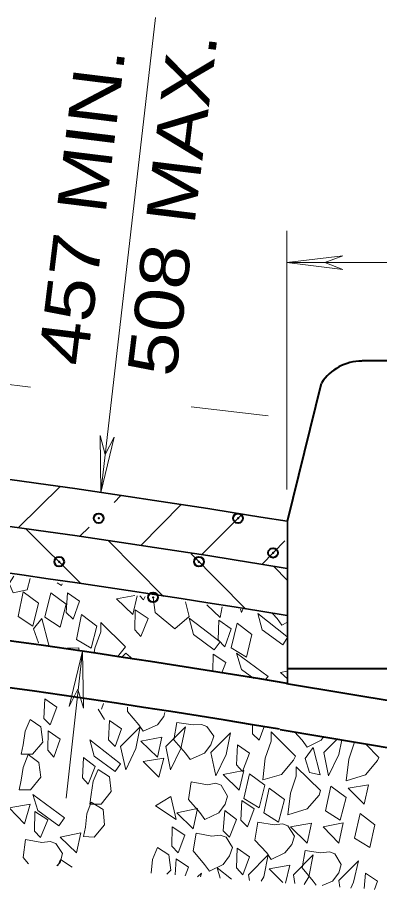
# Model space of a CAD drawing. Extents: x 312583 to 312854, y 144419 to 144597.
# Drawn here: x 312697.85 to 312703.46, y 144439.22 to 144452.74 of the extents above; entities that cross this region are included whole.
import ezdxf

# ---------------------------------------------------------------- set-up
doc = ezdxf.new("R2010")
doc.units = 0
doc.header["$LTSCALE"] = 0.3
doc.header["$PDMODE"] = 32
doc.header["$PDSIZE"] = 0.15
doc.layers.add('1', color=7, linetype='Continuous', lineweight=40)
doc.layers.add('2', color=7, linetype='Continuous', lineweight=13)

msp = doc.modelspace()

# ---------------------------------------------------------------- linework, layer by layer
at = {"layer": '1', "lineweight": 13}
for p, q in [((312697.8645, 144444.8297), (312698.5085, 144445.4661)), ((312699.3442, 144445.2207), (312699.4515, 144445.3281)), ((312699.7582, 144444.5537), (312700.3868, 144445.1901)), ((312700.7012, 144444.4081), (312701.3375, 144445.0444)), ((312697.9718, 144444.8144), (312698.8305, 144443.9634)), ((312698.8152, 144444.6994), (312698.9608, 144444.8374)), ((312699.2522, 144444.6304), (312700.1108, 144443.7641)), ((312701.6442, 144444.2624), (312701.9968, 144444.6227)), ((312700.5402, 144444.4234), (312701.3912, 144443.5647)), ((312701.8205, 144444.2317), (312702.0352, 144444.0094)), ((312699.6662, 144443.7794), (312699.3825, 144443.7257)), ((312699.9498, 144443.7487), (312699.9805, 144443.5111)), ((312701.8052, 144443.4957), (312701.8742, 144443.4191)), ((312698.0945, 144443.2581), (312698.1712, 144443.0434)), ((312699.5282, 144442.8824), (312699.4668, 144442.8211)), ((312699.6355, 144442.7904), (312699.5282, 144442.8824)), ((312700.8852, 144442.8671), (312700.8775, 144442.5987)), ((312701.3222, 144442.6294), (312701.5138, 144442.4914)), ((312702.0275, 144442.6064), (312701.9278, 144442.5834)), ((312701.9278, 144442.5834), (312702.0352, 144442.4837))]:
    msp.add_line(p, q, dxfattribs=at)
for points in [[(312697.7878, 144444.0784), (312697.7188, 144443.9634), (312697.7802, 144443.8177), (312697.9948, 144443.8637), (312698.0408, 144444.0401)], [(312698.5392, 144443.9557), (312698.5315, 144443.9327), (312698.4625, 144443.9711)], [(312699.3825, 144443.7257), (312699.6355, 144443.4804), (312699.7045, 144443.7717)], [(312699.7428, 144443.7717), (312699.8042, 144443.7104), (312699.8272, 144443.7641)], [(312699.9805, 144443.5111), (312700.2872, 144443.2581), (312700.5095, 144443.4497), (312700.4558, 144443.6797)], [(312700.7855, 144443.6337), (312700.9925, 144443.4344), (312701.0232, 144443.6031)], [(312701.3452, 144443.5647), (312701.3222, 144443.5111), (312701.3068, 144443.5647)], [(312698.3322, 144443.0051), (312698.2248, 144443.4191), (312698.0945, 144443.2581)], [(312702.0275, 144443.1431), (312701.5752, 144443.4957), (312701.6442, 144443.2427)], [(312701.8742, 144443.4191), (312701.9508, 144443.3194), (312702.0275, 144443.3577)], [(312699.3978, 144442.8287), (312699.4822, 144442.9284), (312699.5205, 144442.9821), (312699.1372, 144443.3577), (312699.1372, 144443.2121)], [(312699.1372, 144443.2121), (312699.0452, 144442.9591), (312699.0375, 144442.8901)], [(312701.6442, 144443.2427), (312701.9662, 144443.0127), (312702.0275, 144443.1124)], [(312698.6158, 144442.9591), (312698.7998, 144442.9667), (312698.7998, 144442.9284)], [(312701.6902, 144442.4684), (312701.7362, 144442.5221), (312701.2455, 144442.8824), (312701.3222, 144442.6294)], [(312701.0155, 144442.5757), (312701.0768, 144442.7367), (312700.8852, 144442.8671)]]:
    msp.add_lwpolyline(points, dxfattribs=at)
for points in [[(312697.8568, 144443.4497), (312697.9335, 144443.8331), (312698.1712, 144443.6567), (312698.0868, 144443.3041)], [(312698.2708, 144443.4421), (312698.3628, 144443.8177), (312698.6005, 144443.6414), (312698.5085, 144443.2887)], [(312698.6235, 144443.8177), (312698.6005, 144443.5111), (312698.7078, 144443.4114), (312698.8075, 144443.6874)], [(312699.6738, 144443.5571), (312699.6662, 144443.2427), (312699.7582, 144443.1431), (312699.8732, 144443.4191)], [(312698.7615, 144443.0971), (312698.8382, 144443.4804), (312699.0758, 144443.3041), (312698.9915, 144442.9591)], [(312700.5785, 144443.1737), (312700.9005, 144442.9361), (312700.9925, 144443.0587), (312700.5095, 144443.4267)], [(312700.9695, 144443.3961), (312700.9618, 144443.0894), (312701.0615, 144442.9821), (312701.1612, 144443.2581)], [(312701.1612, 144442.9667), (312701.2532, 144443.3501), (312701.4832, 144443.1737), (312701.3988, 144442.8211)]]:
    msp.add_lwpolyline(points, close=True, dxfattribs=at)
at = {"layer": '1'}
for p in [(312699.1065, 144444.9754), (312701.2685, 144444.9754), (312701.8128, 144444.4387), (312698.4932, 144444.3007), (312700.6628, 144444.3007), (312699.9498, 144443.7487)]:
    msp.add_point(p, dxfattribs=at)
at = {"layer": '2'}
for p, q in [((312699.1372, 144445.3741), (312699.9884, 144452.7403)), ((312702.0275, 144445.4201), (312702.0275, 144449.4297)), ((312702.0275, 144448.9391), (312702.8938, 144449.0464)), ((312702.8938, 144449.0464), (312702.6178, 144448.9391)), ((312702.0275, 144448.9391), (312713.1058, 144448.9391)), ((312702.0275, 144448.9391), (312702.8938, 144448.8317)), ((312702.8938, 144448.8317), (312702.6178, 144448.9391)), ((312698.0485, 144447.0071), (312695.7715, 144447.2831)), ((312701.7362, 144446.5624), (312700.5402, 144446.7004)), ((312699.1295, 144446.2557), (312699.2062, 144445.9644)), ((312699.1372, 144445.3741), (312699.1295, 144446.2557)), ((312699.1372, 144445.3741), (312699.3442, 144446.2327)), ((312699.3442, 144446.2327), (312699.2062, 144445.9644)), ((312702.0352, 144442.6447), (312702.0352, 144444.9294)), ((312698.6005, 144440.6361), (312698.8535, 144442.9131)), ((312698.8535, 144442.9131), (312698.6465, 144442.0544)), ((312698.8535, 144442.9131), (312698.8688, 144442.0314)), ((312698.6465, 144442.0544), (312698.7845, 144442.3227)), ((312698.8688, 144442.0314), (312698.7845, 144442.3227)), ((312699.1525, 144442.0161), (312699.1832, 144442.1004)), ((312699.1985, 144441.8551), (312699.0988, 144442.0161)), ((312702.1425, 144441.6634), (312702.2652, 144441.5331)), ((312702.6025, 144441.3414), (312702.8095, 144441.5484)), ((312698.5162, 144439.6854), (312698.4702, 144439.5857)), ((312698.6925, 144439.5627), (312698.5162, 144439.6854)), ((312700.3102, 144439.6931), (312700.2948, 144439.4477)), ((312701.7515, 144439.5397), (312701.9662, 144439.3251)), ((312701.4448, 144439.3557), (312701.4295, 144439.4477)), ((312702.1502, 144439.3097), (312702.1272, 144439.4477)), ((312702.8478, 144439.2561), (312702.8325, 144439.3557)), ((312703.2465, 144439.4707), (312703.2235, 144439.2331)), ((312702.4338, 144439.3481), (312702.4798, 144439.2867))]:
    msp.add_line(p, q, dxfattribs=at)
at = {"layer": '2', "lineweight": 40}
for p, q in [((312704.4425, 144447.4134), (312703.1928, 144447.4134)), ((312702.0352, 144444.9294), (312702.5642, 144447.0684)), ((312702.0352, 144442.6447), (312704.4425, 144442.6447)), ((312702.0198, 144442.4147), (312710.5068, 144440.9887)), ((312701.9202, 144441.7017), (312710.4608, 144440.2681))]:
    msp.add_line(p, q, dxfattribs=at)
at = {"layer": '2', "lineweight": 35}
msp.add_line((312702.0352, 144442.4147), (312702.0352, 144444.9294), dxfattribs=at)
at = {"layer": '2'}
for points in [[(312698.2708, 144442.1771), (312698.2555, 144441.8704), (312698.3552, 144441.7707), (312698.4548, 144442.0467)], [(312698.0408, 144441.8551), (312697.9642, 144441.6711), (312697.9335, 144441.4641), (312697.9028, 144441.3184), (312698.0792, 144441.3184), (312698.2402, 144441.5024), (312698.2095, 144441.7401)], [(312699.2752, 144441.8397), (312699.2598, 144441.5407), (312699.3595, 144441.4334), (312699.4592, 144441.7094)], [(312700.4558, 144441.3337), (312700.5248, 144441.2341), (312700.7472, 144441.3337), (312700.8468, 144441.4641), (312700.8928, 144441.5944), (312700.7855, 144441.7477), (312700.7012, 144441.7784), (312700.5708, 144441.7707), (312700.3178, 144441.8091), (312700.2718, 144441.5407)], [(312698.3245, 144441.6787), (312698.3168, 144441.3797), (312698.4088, 144441.2724), (312698.5085, 144441.5484)], [(312699.4438, 144441.4334), (312699.7505, 144441.7401), (312699.6815, 144441.4027), (312699.5282, 144441.0731)], [(312700.1492, 144441.4334), (312700.4558, 144441.7401), (312700.3792, 144441.4027), (312700.2182, 144441.0731)], [(312701.7822, 144441.5177), (312701.6902, 144441.2571), (312701.6518, 144440.9197), (312701.9432, 144441.0041), (312702.1272, 144441.2264), (312702.1578, 144441.2877), (312701.7822, 144441.6634)], [(312699.0375, 144441.2877), (312699.3595, 144441.0501), (312699.4438, 144441.1651), (312698.9685, 144441.5407)], [(312699.7582, 144441.5177), (312700.0188, 144441.2724), (312700.0878, 144441.5791)], [(312700.8468, 144441.3414), (312701.1535, 144441.6481), (312701.0845, 144441.3107), (312700.9235, 144440.9811)], [(312701.2608, 144441.4641), (312701.2455, 144441.1497), (312701.3375, 144441.0501), (312701.4448, 144441.3337)], [(312702.3112, 144441.2494), (312702.3802, 144441.0347), (312702.5412, 144440.9964), (312702.4338, 144441.4181)], [(312698.0102, 144441.3107), (312697.9335, 144441.1114), (312697.9028, 144440.9121), (312697.8722, 144440.7664), (312698.0485, 144440.7664), (312698.2095, 144440.9581), (312698.1788, 144441.1881)], [(312698.8688, 144441.2647), (312698.8535, 144440.9504), (312698.9455, 144440.8507), (312699.0528, 144441.1267)], [(312699.7965, 144441.2034), (312700.0418, 144440.9581), (312700.1185, 144441.2571)], [(312702.1732, 144440.9734), (312702.0812, 144440.7127), (312702.0428, 144440.3754), (312702.3418, 144440.4674), (312702.5258, 144440.6821), (312702.5488, 144440.7511), (312702.1732, 144441.1191)], [(312699.0988, 144441.0807), (312699.0222, 144440.8967), (312698.9915, 144440.6897), (312698.9685, 144440.5441), (312699.1448, 144440.5441), (312699.2982, 144440.7357), (312699.2752, 144440.9657)], [(312701.0385, 144441.0041), (312701.2838, 144440.7587), (312701.3605, 144441.0654)], [(312701.3605, 144440.6284), (312701.4448, 144441.0117), (312701.6825, 144440.8354), (312701.5982, 144440.4827)], [(312700.6782, 144440.4137), (312700.7548, 144440.3064), (312700.9695, 144440.4061), (312701.0692, 144440.5441), (312701.1075, 144440.6667), (312701.0078, 144440.8354), (312700.9235, 144440.8661), (312700.7932, 144440.8431), (312700.5402, 144440.8891), (312700.5018, 144440.6131)], [(312702.9782, 144440.7894), (312703.2235, 144440.5441), (312703.2925, 144440.8431)], [(312701.6672, 144440.4061), (312701.7515, 144440.7894), (312701.9892, 144440.6131), (312701.8972, 144440.2604)], [(312702.6255, 144440.4367), (312702.7098, 144440.8201), (312702.9475, 144440.6437), (312702.8555, 144440.2911)], [(312698.1635, 144440.4444), (312698.4855, 144440.2067), (312698.5775, 144440.3294), (312698.0868, 144440.6897)], [(312698.9915, 144440.5747), (312698.9225, 144440.3907), (312698.8995, 144440.1837), (312698.8688, 144440.0381), (312699.0375, 144440.0304), (312699.1985, 144440.2221), (312699.1755, 144440.4597)], [(312699.9882, 144440.5134), (312700.3102, 144440.3064), (312700.2258, 144440.6591)], [(312701.3298, 144440.5977), (312701.3145, 144440.2911), (312701.4142, 144440.1914), (312701.5215, 144440.4674)], [(312697.7188, 144440.4827), (312697.9565, 144440.2374), (312698.0408, 144440.5441)], [(312700.3178, 144440.4061), (312700.5708, 144440.1607), (312700.6398, 144440.4751)], [(312701.0615, 144440.4444), (312701.0385, 144440.1301), (312701.1382, 144440.0304), (312701.2455, 144440.3064)], [(312698.1175, 144440.4291), (312698.1098, 144440.1224), (312698.2018, 144440.0227), (312698.3168, 144440.2987)], [(312703.0778, 144440.0151), (312703.1622, 144440.3984), (312703.3922, 144440.2221), (312703.3155, 144439.8694)], [(312700.2488, 144440.1914), (312700.2412, 144439.8924), (312700.3408, 144439.7851), (312700.4405, 144440.0611)], [(312701.7132, 144439.7851), (312701.7822, 144439.6854), (312701.9968, 144439.7851), (312702.1042, 144439.9154), (312702.1425, 144440.0457), (312702.0428, 144440.2067), (312701.9585, 144440.2374), (312701.8282, 144440.2221), (312701.5752, 144440.2604), (312701.5292, 144439.9844)], [(312702.0812, 144440.1914), (312702.3418, 144439.9384), (312702.4108, 144440.2451)], [(312702.5872, 144440.1914), (312702.8325, 144439.9384), (312702.9015, 144440.2527)], [(312698.5085, 144440.0304), (312698.7615, 144439.7851), (312698.8305, 144440.0994)], [(312700.7472, 144439.6087), (312700.8238, 144439.5014), (312701.0385, 144439.6087), (312701.1382, 144439.7391), (312701.1842, 144439.8694), (312701.0845, 144440.0304), (312700.9925, 144440.0611), (312700.8622, 144440.0457), (312700.6168, 144440.0917), (312700.5708, 144439.8157)], [(312701.2532, 144439.8617), (312701.2455, 144439.5551), (312701.3452, 144439.4477), (312701.4448, 144439.7237)]]:
    msp.add_lwpolyline(points, close=True, dxfattribs=at)
for points in [[(312699.5512, 144442.0467), (312699.5512, 144441.9777), (312699.7275, 144441.7707)], [(312699.7275, 144441.7707), (312699.7965, 144441.6711), (312700.0188, 144441.7707), (312700.1185, 144441.9011), (312700.1338, 144441.9624)], [(312701.4908, 144441.7554), (312701.4908, 144441.6327), (312701.5982, 144441.5331), (312701.6672, 144441.7324)], [(312702.2652, 144441.5331), (312702.3418, 144441.4257), (312702.5565, 144441.5331), (312702.5948, 144441.5867)], [(312702.8785, 144441.5407), (312702.8325, 144441.3107), (312702.6715, 144440.9811), (312702.6025, 144441.3414)], [(312703.0778, 144441.5024), (312702.9858, 144441.2417), (312702.9475, 144440.9044), (312703.2465, 144440.9964), (312703.4305, 144441.2187), (312703.4535, 144441.2647), (312703.2542, 144441.4717)], [(312698.4548, 144439.5857), (312698.5085, 144439.6394), (312698.5468, 144439.7774), (312698.4395, 144439.9307), (312698.3552, 144439.9614), (312698.2248, 144439.9461), (312697.9718, 144439.9921), (312697.9335, 144439.7161), (312698.0178, 144439.6164)], [(312700.0188, 144439.8694), (312699.9422, 144439.6854), (312699.9192, 144439.4707)], [(312700.1645, 144439.4554), (312700.2258, 144439.5167), (312700.1952, 144439.7544), (312700.0188, 144439.8694)], [(312702.5718, 144439.2791), (312702.7328, 144439.3481), (312702.8325, 144439.4784), (312702.8708, 144439.6087), (312702.7712, 144439.7697), (312702.6868, 144439.8004), (312702.5488, 144439.7851), (312702.3112, 144439.8234), (312702.2652, 144439.5551), (312702.4338, 144439.3481)], [(312700.4482, 144439.4324), (312700.5018, 144439.5627), (312700.3102, 144439.6931)], [(312701.4295, 144439.4477), (312701.7362, 144439.7544), (312701.6672, 144439.4171), (312701.6288, 144439.3481)], [(312702.1272, 144439.4477), (312702.4338, 144439.7544), (312702.3648, 144439.4171), (312702.2958, 144439.2944)], [(312702.8325, 144439.3557), (312703.1392, 144439.6624), (312703.0625, 144439.3327), (312703.0165, 144439.2407)], [(312701.1688, 144439.3787), (312700.9465, 144439.5551), (312700.9925, 144439.3941)], [(312702.0045, 144439.3174), (312702.0735, 144439.5934), (312701.7515, 144439.5397)], [(312700.6398, 144439.4171), (312700.7012, 144439.4707), (312700.6858, 144439.4171)], [(312703.3845, 144439.2177), (312703.4305, 144439.3481), (312703.2465, 144439.4707)]]:
    msp.add_lwpolyline(points, dxfattribs=at)
at = {"layer": '2', "lineweight": 40}
for centre, radius, start, end in [((312703.1919, 144446.6602), 0.7515, 90.04504, 146.80695), ((312674.349, 144275.8703), 168.8299, 80.56235, 89.88555), ((312674.349, 144275.8703), 168.1094, 80.56235, 89.88555)]:
    msp.add_arc(centre, radius, start, end, dxfattribs=at)
at = {"layer": '2', "lineweight": 35}
for radius, start, end in [(171.3086, 80.70018, 89.61922), (170.5881, 80.66055, 89.61762), (169.8675, 80.62058, 89.61599)]:
    msp.add_arc((312674.349, 144275.8703), radius, start, end, dxfattribs=at)

# ---------------------------------------------------------------- texts
at = {"layer": '2', "width": 1.2}
for s, p in [('508 MAX.', (312700.3005, 144447.1488)), ('457 MIN.', (312698.9205, 144447.3175))]:
    msp.add_text(s, height=0.76, rotation=83, dxfattribs=at).set_placement(p)

doc.saveas('drawing.dxf')
